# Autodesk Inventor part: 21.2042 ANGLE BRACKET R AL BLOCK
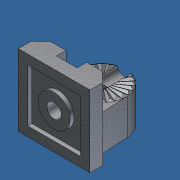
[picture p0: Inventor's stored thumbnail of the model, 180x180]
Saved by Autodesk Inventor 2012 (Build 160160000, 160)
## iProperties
Created: 2007-01
Part Number: 21.2042 ANGLE BRACKET R AL BLOCK
Document SubType Name: Modeling
Designer: Andy Moles
Material: Aluminum-6061
Density: 2.71 g/cm^3
Mass: 103.451 g
Surface Area: 106.978 cm^2
Volume: 38.1736 cm^3
Author: Andy Moles
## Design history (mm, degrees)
sketch "Sketch1"
  geometry: L1 (-22.5, 0)-(22.5, 0); L2 (-22.5, 0)-(-22.5, 8); L3 (22.5, 0)-(22.5, 8); L4 (-16, 14)-(-14.972, 30.91); L5 (16, 14)-(14.972, 30.91); L6 (-22.5, 8)-(-16, 14); L7 (22.5, 8)-(16, 14); C1 r 4.1 at (0, 30); A1 r 15 centre (0, 30) between (14.972, 30.91) and (-14.972, 30.91); 2 further points
  constraints: 14 end point, 2 centre point, 2 coincident, 2 equal length, 2 point on circle, 2 tangent, 1 horizontal, 1 horizontal alignment, 1 midpoint, 1 parallel, 1 perpendicular
  dimensions: "d0" = 45 distance of L1.start L1.end; "d1" = 8.2 diameter of C1; "d2" = 30 distance from line of L1 C1.centre; "d3" = 30 diameter of A1; "d4" = 8 distance of L1.start L2.end; "d5" = 8 distance of L1.end L3.end; "d18" = 14.97238 horizontal distance of point (0, 0) L4.end (derived); "d19" = 14.97238 horizontal distance of L5.end point (0, 0) (derived); "d22" = 32 distance of L5.start L4.start; "d23" = 14 distance from line of L1 L5.start
extrude "Extrusion1" new body sketch "Sketch1" distance "d8" = 45; taper "d9" = 0 deg
sketch "Sketch5"
  geometry: L1 (6, 6)-(39, 6); L2 (39, 6)-(39, 39); L3 (39, 39)-(6, 39); L4 (6, 39)-(6, 6); L5 (6, 6)-(39, 39); C1 r 10 at (22.5, 22.5); C2 r 4.5 at (22.5, 22.5); 2 further points
  constraints: 10 end point, 2 centre point, 2 coincident, 2 parallel, 1 horizontal, 1 midpoint, 1 perpendicular
  dimensions: "d24" = 33 distance of L2.end L3.end; "d25" = 33 distance of L3.end L1.start; "d26" = 20 diameter of C1; "d52" = 9 diameter of C2
extrude "Extrusion5" cut sketch "Sketch5" distance "d27" = 2.5; taper "d28" = 0 deg
sketch "Sketch2"
  geometry: L1 (16, 59.717)-(-16, 59.717); L2 (22.5, 8)-(22.5, 0) reference; L3 (-16, 14)-(16, 14); L4 (-16, 14)-(-16, 59.717); L5 (16, 14)-(16, 59.717); C1 r 4.1 at (0, 30) reference; 1 further point
  constraints: 8 end point, 3 perpendicular
extrude "Extrusion2" cut sketch "Sketch2" distance "d10" = 22.5; taper "d11" = 0 deg
sketch "Sketch4"
  geometry: L1 (0, -45)-(45, -45); L2 (9.5, 22.5)-(9.5, -45); L3 (22.5, 22.5)-(22.5, -45); L4 (9.5, -45)-(22.5, -45); A1 r 45.044 centre (16, 22.5) between (18, -22.5) and (26.696, -21.256); A2 r 6.5 centre (16, 22.5) between (22.5, 22.5) and (9.5, 22.5); 1 further point
  constraints: 8 end point, 4 point on circle, 3 perpendicular, 2 centre point, 2 tangent, 1 coincident, 1 midpoint, 1 point on line
  dimensions: "d15" = 13 diameter of A2
extrude "Extrusion4" cut sketch "Sketch4" distance "d16" = 6; taper "d17" = 0 deg
sketch "Sketch6"
  geometry: L1 (-22.5, 0)-(-22.5, 8) reference; L2 (-7.433, 29.742)-(-3.565, 36.442); L3 (-3.565, 36.442)-(4.172, 36.442); L4 (4.172, 36.442)-(8.04, 29.742); L5 (8.04, 29.742)-(4.172, 23.042); L6 (4.172, 23.042)-(-3.565, 23.042); L7 (-3.565, 23.042)-(-7.433, 29.742); C1 r 4.1 at (0, 30); C2 r 4.1 at (0, 30) reference; A1 r 15 centre (0, 30) between (14.972, 30.91) and (-14.972, 30.91) reference; 1 further point
  constraints: 12 end point, 3 equal length, 2 parallel, 1 centre point, 1 coincident, 1 concentric, 1 perpendicular
  dimensions: "d32" = 120 deg angle of L2 L7; "d33" = 120 deg angle of L4 L3; "d34" = 120 deg angle of L5 L4; "d35" = 120 deg angle of L6 L7 (derived); "d36" = 13.4 distance between parallel lines of L5 L2
extrude "Extrusion6" cut sketch "Sketch6" distance "d37" = 10; taper "d38" = 0 deg
sketch "Sketch7"
  geometry: L1 (0, 30)-(-18.476, 30); L2 (0, 30)-(-14.872, 31.958); L3 (0, 30)-(-14.872, 28.042); A1 r 15 centre (0, 30) between (-14.872, 31.958) and (-14.872, 28.042); 1 further point
  constraints: 6 end point, 2 point on circle, 1 centre point, 1 coincident, 1 horizontal
  dimensions: "d42" = 7.5 deg angle of L2 L1; "d43" = 7.5 deg angle of L1 L3; "d53" = 15 radius of A1
extrude "Extrusion7" join sketch "Sketch7" distance "d44" = 1; taper "d45" = -60 deg
sketch "Sketch8"
  geometry: C1 r 10 at (0, 0) reference; C2 r 4.5 at (0, 0); 1 further point
  constraints: 1 centre point, 1 coincident
  dimensions: "d49" = 9 diameter of C2
extrude "Extrusion8" cut sketch "Sketch8" stored distance "d50" = 1; taper "d51" = 0 deg
fillet "Fillet2" dims "d54" = 34
body "Solid1"
pattern_circular "Circular Pattern1" dims angle "d47" = 360 deg
